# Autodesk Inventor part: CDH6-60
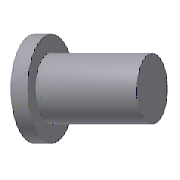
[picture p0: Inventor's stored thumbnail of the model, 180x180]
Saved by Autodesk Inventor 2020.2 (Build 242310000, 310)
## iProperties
Manager: www.cadconsulting.pl
Company: Fabian Stasiak CAD Consulting
Created: 2014-02
Part Number: CDH6-60
Material: SKD61
Description: Straight Core Pin
Document SubType Name: Modeling
Designer: F.Stasiak
Standard Revision: 1
Manufacturer: PUNCH
Language: pl-PL
Size Designation: 6-60
Categories: <MemberInstance><Categories><Category DisplayName="Forma wtryskowa" InternalName="349578f2-f4d4-4954-8c09-8e99297a61c0" Mnemonic="MOLD"><Category DisplayName="W
Mass: 1.61494 g
Surface Area: 11.4822 cm^2
Volume: 1.61494 cm^3
Density: 7.8 g/cm^3
Appearance: Aluminium - ciemne
Catalog Web Link: www.expertbooks.pl
IsCustomPart: 1
Author: F.Stasiak
Subject: Zbiór ćwiczeń. Autodesk Inventor 2020. Kurs Professional
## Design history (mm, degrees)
sketch "Sketch1"
  geometry: L1 (4.5, 0)-(4.5, 4); L2 (4.5, 4)-(3, 4); L3 (3, 4)-(3, 60); L4 (3, 60)-(0, 60); L5 (4.5, 0)-(0, 0); L6 (0, 0)-(0, 60); L7 (0, 60)-(0, -10) reference; 1 further point
  constraints: 14 end point, 2 horizontal, 1 coincident, 1 collinear, 1 parallel
  dimensions: "d2" = 4 distance of L1.start L1.end (= T_); "d19" = 60 distance between parallel lines of L4 L5 (= L); "d38" = 6 diameter of L3 L7 (= P); "d39" = 9 diameter of L1 L7 (= H_)
revolve "Revolution1" sketch "Sketch1" stored, may be unused: angle "d4" = 90 deg
fillet "Fillet1" dims "d36" = 0.3
workplane "Work Plane1"
sketch "Sketch2"
  geometry: 2 further points
  constraints: 1 vertical alignment
  dimensions: "d21" = 2 distance of point (0, -2) point (0, 0) (= 0.5 x T_)
hole "Anti_Rotary Hole" sketch "Sketch2" at (0, 0) diameter "d22" = 0.8 (= Anti_Rotary_D); stored, may be unused: countersink angle "d26" = 90 deg, drill point angle "d28" = 118 deg; dims "d23" = 6, "d24" = 4, "d25" = 2, "d27" = 1.2 (= 1.5 x Anti_Rotary_D)
sketch "Sketch3"
  geometry: L1 (-3.3, 3.059)-(-3.3, -3.059); A1 r 4.5 centre (0, 0) between (-3.3, 3.059) and (-3.3, -3.059) reference; 1 further point
  constraints: 2 end point, 2 point on circle, 1 vertical
  dimensions: "d29" = 3.3 distance from line of point (0, 0) L1 (= Anti_Rotary_P)
extrude "Anti_Rotary Plane" cut sketch "Sketch3" extent not by distance; stored distance "d30" = 10; taper "d31" = 0 deg
feature "Rzeźbienie1"
body "Solid1"
feature "Powierzchnia1"
body "Srf1"
other parameters: "H_" = 9 [user parameter; used in 1 equation term], "L" = 60 [user parameter; used in 1 equation term], "P" = 6 [user parameter; used in 1 equation term], "d7" = 0, "d8" = 0, "T_" = 4 [user parameter; used in 2 equation terms], "Anti_Rotary_P" = 3.3 [user parameter; used in 1 equation term], "Anti_Rotary_D" = 0.8 [user parameter; used in 2 equation terms], "d32" = 0, "d33" = 0, "d34" = 0, "d35" = 0, "IsARPlane" = 0 [user parameter], "IsARHole" = 0 [user parameter]
